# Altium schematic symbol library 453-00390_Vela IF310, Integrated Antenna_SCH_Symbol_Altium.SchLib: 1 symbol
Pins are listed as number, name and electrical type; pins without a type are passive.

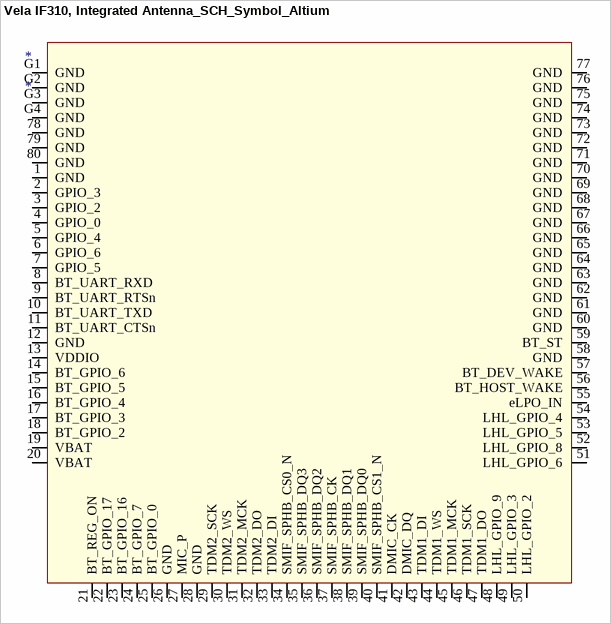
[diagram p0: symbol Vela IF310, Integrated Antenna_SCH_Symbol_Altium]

## Vela IF310, Integrated Antenna_SCH_Symbol_Altium
designator *
pins: 1 GND, 2 GPIO_3, 3 GPIO_2, 4 GPIO_0, 5 GPIO_4, 6 GPIO_6, 7 GPIO_5, 8 BT_UART_RXD, 9 BT_UART_RTSn, 10 BT_UART_TXD, 11 BT_UART_CTSn, 12 GND, 13 VDDIO, 14 BT_GPIO_6, 15 BT_GPIO_5, 16 BT_GPIO_4, 17 BT_GPIO_3, 18 BT_GPIO_2, 19 VBAT, 20 VBAT, 21 BT_REG_ON, 22 BT_GPIO_17, 23 BT_GPIO_16, 24 BT_GPIO_7, 25 BT_GPIO_0, 26 GND, 27 MIC_P, 28 GND, 29 TDM2_SCK, 30 TDM2_WS, 31 TDM2_MCK, 32 TDM2_DO, 33 TDM2_DI, 34 SMIF_SPHB_CS0_N, 35 SMIF_SPHB_DQ3, 36 SMIF_SPHB_DQ2, 37 SMIF_SPHB_CK, 38 SMIF_SPHB_DQ1, 39 SMIF_SPHB_DQ0, 40 SMIF_SPHB_CS1_N, 41 DMIC_CK, 42 DMIC_DQ, 43 TDM1_DI, 44 TDM1_WS, 45 TDM1_MCK, 46 TDM1_SCK, 47 TDM1_DO, 48 LHL_GPIO_9, 49 LHL_GPIO_3, 50 LHL_GPIO_2, 51 LHL_GPIO_6, 52 LHL_GPIO_8, 53 LHL_GPIO_5, 54 LHL_GPIO_4, 55 eLPO_IN, 56 BT_HOST_WAKE, 57 BT_DEV_WAKE, 58 GND, 59 BT_ST, 60 GND, 61 GND, 62 GND, 63 GND, 64 GND, 65 GND, 66 GND, 67 GND, 68 GND, 69 GND, 70 GND, 71 GND, 72 GND, 73 GND, 74 GND, 75 GND, 76 GND, 77 GND, 78 GND, 79 GND, 80 GND, G1 GND, G2 GND, G3 GND, G4 GND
